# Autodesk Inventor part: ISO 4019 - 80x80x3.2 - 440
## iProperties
Created: 2007-05
Part Number: ISO 4019 - 80x80x3.2 - 440
Material: Steel, Mild
Description: Cold-Finished Hollow Section
Vendor: Autodesk Inc.
Document SubType Name: Modeling
Standard: ISO 4019
Designer: kurs1
Standards Organization: ISO
Language: en-US
Size Designation: 80x80x3.2 - 440
Categories: <MemberInstance Version="R10.0.0"><Categories><Category DisplayName="Steel Shapes" InternalName="089c4875-fa83-4c05-b084-43b9cc11f5ed" Mnemonic="GRDR"><Category
Stock Number: 80x80x3.2
Density: 1 g/cm^3
G_L: 440,000 mm
Author: kurs1
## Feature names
1. Body [Extrusion]
2. Fillet1
3. Fillet2
